(* Logix 5000 project; controller MyControlLogix 1756-L63 rev 15.1; software revision 15.02; part 3 of 4 *)
(* tags used below, declared in another part *)
   AFC56 : AFC;
(* MainProgram, continued *)

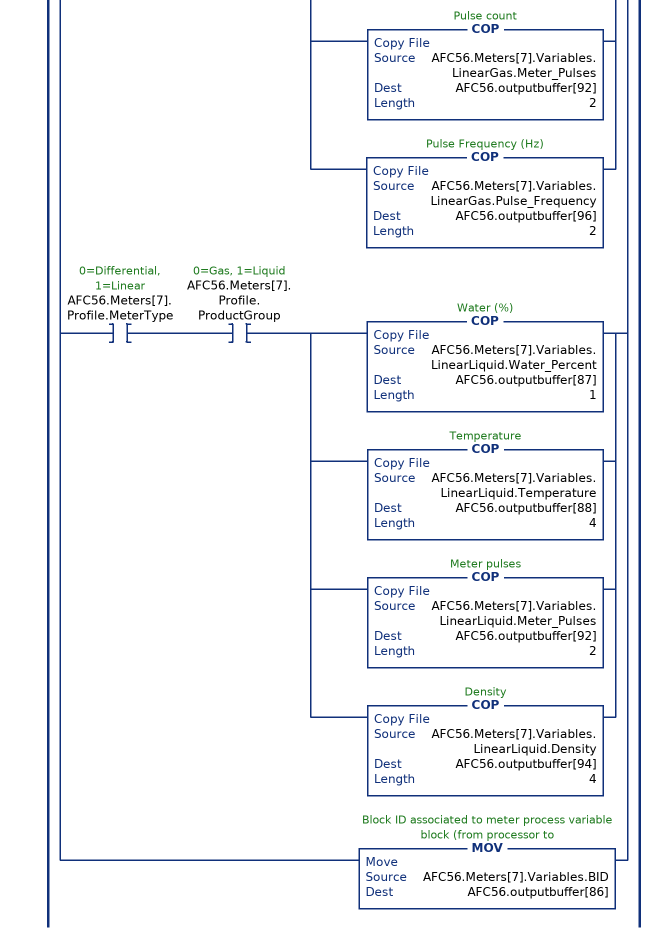
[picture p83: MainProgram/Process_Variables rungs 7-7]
   7: [ADD(8,8192,AFC56.Meters[7].Variables.BID) ,XIO(AFC56.EnableStatus.Meter8) [OTE(AFC56.Meters[7].Variables.BID.8) ,OTU(AFC56.DisableMeter.Meter8) ] ,XIC(AFC56.EnableStatus.Meter8) OTU(AFC56.EnableMeter.Meter8) ,XIO(AFC56.Meters[7].Profile.MeterType) XIO(AFC56.Meters[7].Profile.ProductGroup) COP(AFC56.Meters[7].Variables.DifferentialGas.Temperature,AFC56.outputbuffer[88],6) ,XIO(AFC56.Meters[7].Profile.MeterType) XIC(AFC56.Meters[7].Profile.ProductGroup) [COP(AFC56.Meters[7].Variables.DifferentialLiquid.Water_Percent,AFC56.outputbuffer[87],1) ,COP(AFC56.Meters[7].Variables.DifferentialLiquid.Temperature,AFC56.outputbuffer[88],8) ] ,XIC(AFC56.Meters[7].Profile.MeterType) XIO(AFC56.Meters[7].Profile.ProductGroup) [COP(AFC56.Meters[7].Variables.LinearGas.Temperature,AFC56.outputbuffer[88],4) ,COP(AFC56.Meters[7].Variables.LinearGas.Meter_Pulses,AFC56.outputbuffer[92],2) ,COP(AFC56.Meters[7].Variables.LinearGas.Pulse_Frequency,AFC56.outputbuffer[96],2) ] ,XIC(AFC56.Meters[7].Profile.MeterType) XIC(AFC56.Meters[7].Profile.ProductGroup) [COP(AFC56.Meters[7].Variables.LinearLiquid.Water_Percent,AFC56.outputbuffer[87],1) ,COP(AFC56.Meters[7].Variables.LinearLiquid.Temperature,AFC56.outputbuffer[88],4) ,COP(AFC56.Meters[7].Variables.LinearLiquid.Meter_Pulses,AFC56.outputbuffer[92],2) ,COP(AFC56.Meters[7].Variables.LinearLiquid.Density,AFC56.outputbuffer[94],4) ] ,MOV(AFC56.Meters[7].Variables.BID,AFC56.outputbuffer[86]) ];
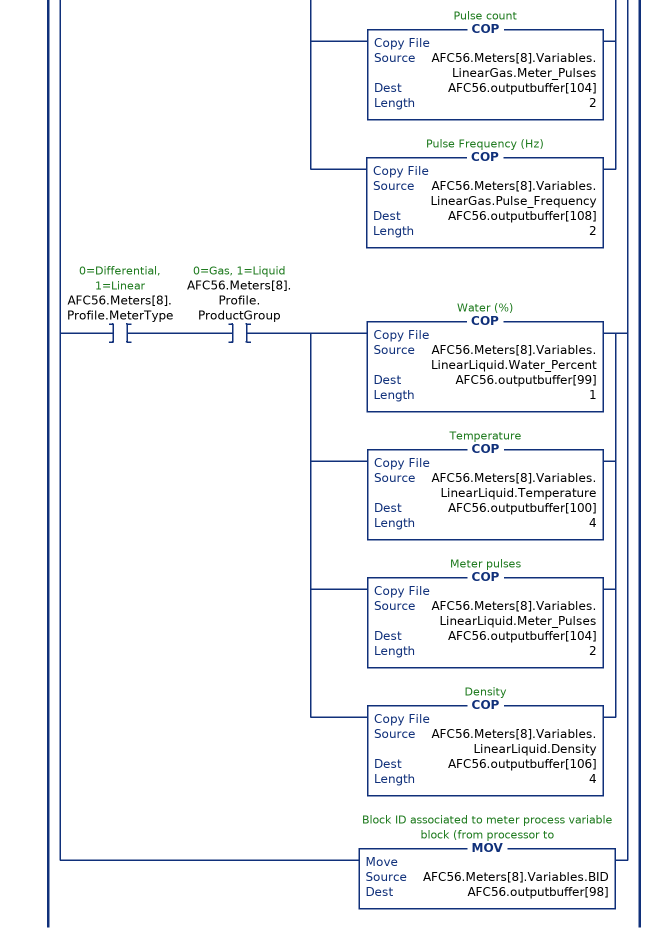
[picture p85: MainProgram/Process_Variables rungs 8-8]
   8: [ADD(9,8192,AFC56.Meters[8].Variables.BID) ,XIO(AFC56.EnableStatus.Meter9) [OTE(AFC56.Meters[8].Variables.BID.8) ,OTU(AFC56.DisableMeter.Meter9) ] ,XIC(AFC56.EnableStatus.Meter9) OTU(AFC56.EnableMeter.Meter9) ,XIO(AFC56.Meters[8].Profile.MeterType) XIO(AFC56.Meters[8].Profile.ProductGroup) COP(AFC56.Meters[8].Variables.DifferentialGas.Temperature,AFC56.outputbuffer[100],6) ,XIO(AFC56.Meters[8].Profile.MeterType) XIC(AFC56.Meters[8].Profile.ProductGroup) [COP(AFC56.Meters[8].Variables.DifferentialLiquid.Water_Percent,AFC56.outputbuffer[99],1) ,COP(AFC56.Meters[8].Variables.DifferentialLiquid.Temperature,AFC56.outputbuffer[100],8) ] ,XIC(AFC56.Meters[8].Profile.MeterType) XIO(AFC56.Meters[8].Profile.ProductGroup) [COP(AFC56.Meters[8].Variables.LinearGas.Temperature,AFC56.outputbuffer[100],4) ,COP(AFC56.Meters[8].Variables.LinearGas.Meter_Pulses,AFC56.outputbuffer[104],2) ,COP(AFC56.Meters[8].Variables.LinearGas.Pulse_Frequency,AFC56.outputbuffer[108],2) ] ,XIC(AFC56.Meters[8].Profile.MeterType) XIC(AFC56.Meters[8].Profile.ProductGroup) [COP(AFC56.Meters[8].Variables.LinearLiquid.Water_Percent,AFC56.outputbuffer[99],1) ,COP(AFC56.Meters[8].Variables.LinearLiquid.Temperature,AFC56.outputbuffer[100],4) ,COP(AFC56.Meters[8].Variables.LinearLiquid.Meter_Pulses,AFC56.outputbuffer[104],2) ,COP(AFC56.Meters[8].Variables.LinearLiquid.Density,AFC56.outputbuffer[106],4) ] ,MOV(AFC56.Meters[8].Variables.BID,AFC56.outputbuffer[98]) ];
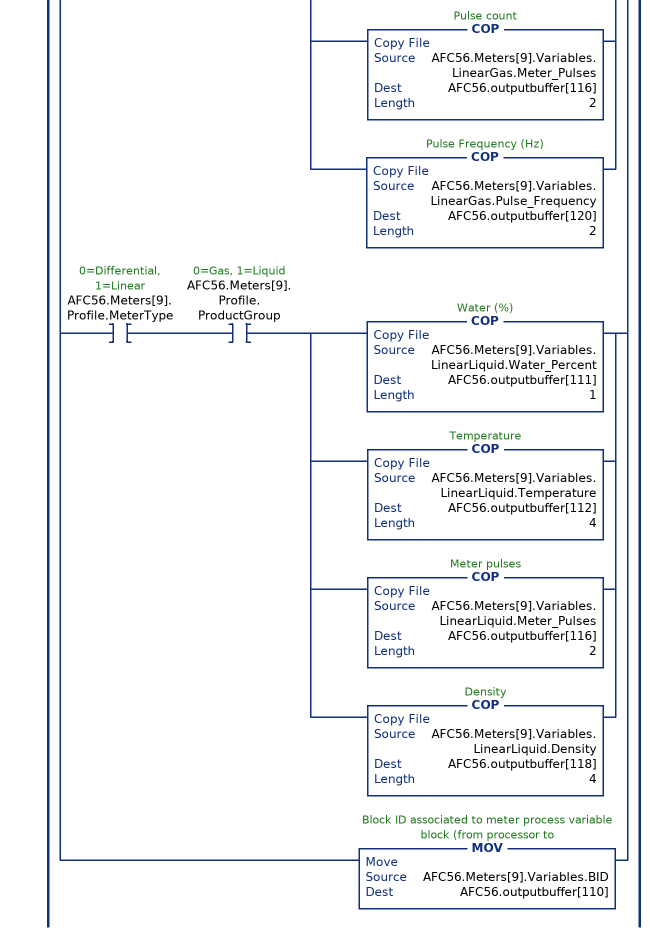
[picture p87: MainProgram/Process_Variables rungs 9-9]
   9: [ADD(10,8192,AFC56.Meters[9].Variables.BID) ,XIO(AFC56.EnableStatus.Meter10) [OTE(AFC56.Meters[9].Variables.BID.8) ,OTU(AFC56.DisableMeter.Meter10) ] ,XIC(AFC56.EnableStatus.Meter10) OTU(AFC56.EnableMeter.Meter10) ,XIO(AFC56.Meters[9].Profile.MeterType) XIO(AFC56.Meters[9].Profile.ProductGroup) COP(AFC56.Meters[9].Variables.DifferentialGas.Temperature,AFC56.outputbuffer[112],6) ,XIO(AFC56.Meters[9].Profile.MeterType) XIC(AFC56.Meters[9].Profile.ProductGroup) [COP(AFC56.Meters[9].Variables.DifferentialLiquid.Water_Percent,AFC56.outputbuffer[111],1) ,COP(AFC56.Meters[9].Variables.DifferentialLiquid.Temperature,AFC56.outputbuffer[112],8) ] ,XIC(AFC56.Meters[9].Profile.MeterType) XIO(AFC56.Meters[9].Profile.ProductGroup) [COP(AFC56.Meters[9].Variables.LinearGas.Temperature,AFC56.outputbuffer[112],4) ,COP(AFC56.Meters[9].Variables.LinearGas.Meter_Pulses,AFC56.outputbuffer[116],2) ,COP(AFC56.Meters[9].Variables.LinearGas.Pulse_Frequency,AFC56.outputbuffer[120],2) ] ,XIC(AFC56.Meters[9].Profile.MeterType) XIC(AFC56.Meters[9].Profile.ProductGroup) [COP(AFC56.Meters[9].Variables.LinearLiquid.Water_Percent,AFC56.outputbuffer[111],1) ,COP(AFC56.Meters[9].Variables.LinearLiquid.Temperature,AFC56.outputbuffer[112],4) ,COP(AFC56.Meters[9].Variables.LinearLiquid.Meter_Pulses,AFC56.outputbuffer[116],2) ,COP(AFC56.Meters[9].Variables.LinearLiquid.Density,AFC56.outputbuffer[118],4) ] ,MOV(AFC56.Meters[9].Variables.BID,AFC56.outputbuffer[110]) ];
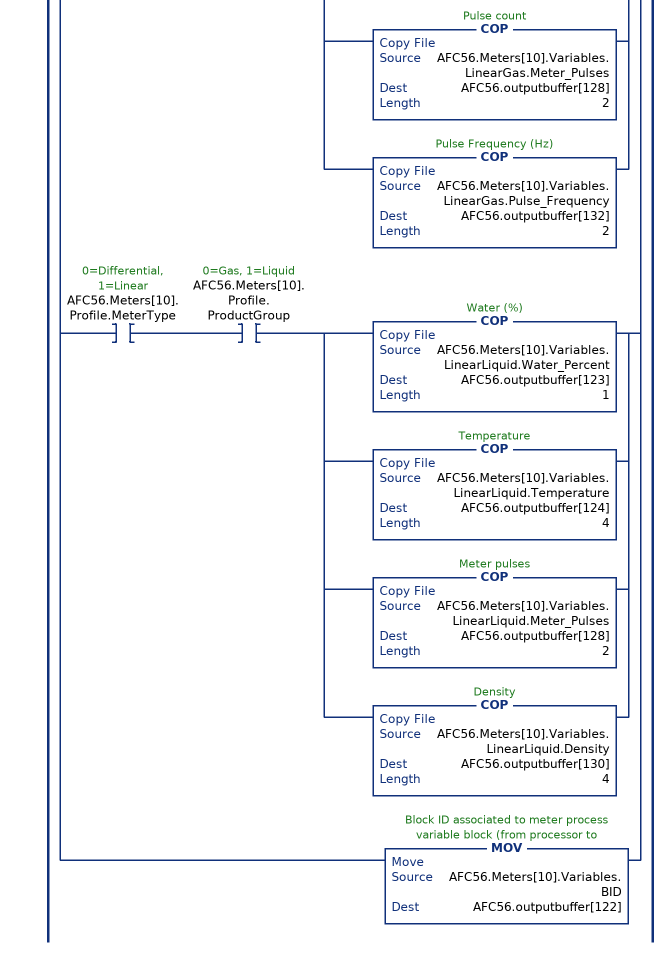
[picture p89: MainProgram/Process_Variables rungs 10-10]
   10: [ADD(11,8192,AFC56.Meters[10].Variables.BID) ,XIO(AFC56.EnableStatus.Meter11) [OTE(AFC56.Meters[10].Variables.BID.8) ,OTU(AFC56.DisableMeter.Meter11) ] ,XIC(AFC56.EnableStatus.Meter11) OTU(AFC56.EnableMeter.Meter11) ,XIO(AFC56.Meters[10].Profile.MeterType) XIO(AFC56.Meters[10].Profile.ProductGroup) COP(AFC56.Meters[10].Variables.DifferentialGas.Temperature,AFC56.outputbuffer[124],6) ,XIO(AFC56.Meters[10].Profile.MeterType) XIC(AFC56.Meters[10].Profile.ProductGroup) [COP(AFC56.Meters[10].Variables.DifferentialLiquid.Water_Percent,AFC56.outputbuffer[123],1) ,COP(AFC56.Meters[10].Variables.DifferentialLiquid.Temperature,AFC56.outputbuffer[124],8) ] ,XIC(AFC56.Meters[10].Profile.MeterType) XIO(AFC56.Meters[10].Profile.ProductGroup) [COP(AFC56.Meters[10].Variables.LinearGas.Temperature,AFC56.outputbuffer[124],4) ,COP(AFC56.Meters[10].Variables.LinearGas.Meter_Pulses,AFC56.outputbuffer[128],2) ,COP(AFC56.Meters[10].Variables.LinearGas.Pulse_Frequency,AFC56.outputbuffer[132],2) ] ,XIC(AFC56.Meters[10].Profile.MeterType) XIC(AFC56.Meters[10].Profile.ProductGroup) [COP(AFC56.Meters[10].Variables.LinearLiquid.Water_Percent,AFC56.outputbuffer[123],1) ,COP(AFC56.Meters[10].Variables.LinearLiquid.Temperature,AFC56.outputbuffer[124],4) ,COP(AFC56.Meters[10].Variables.LinearLiquid.Meter_Pulses,AFC56.outputbuffer[128],2) ,COP(AFC56.Meters[10].Variables.LinearLiquid.Density,AFC56.outputbuffer[130],4) ] ,MOV(AFC56.Meters[10].Variables.BID,AFC56.outputbuffer[122]) ];
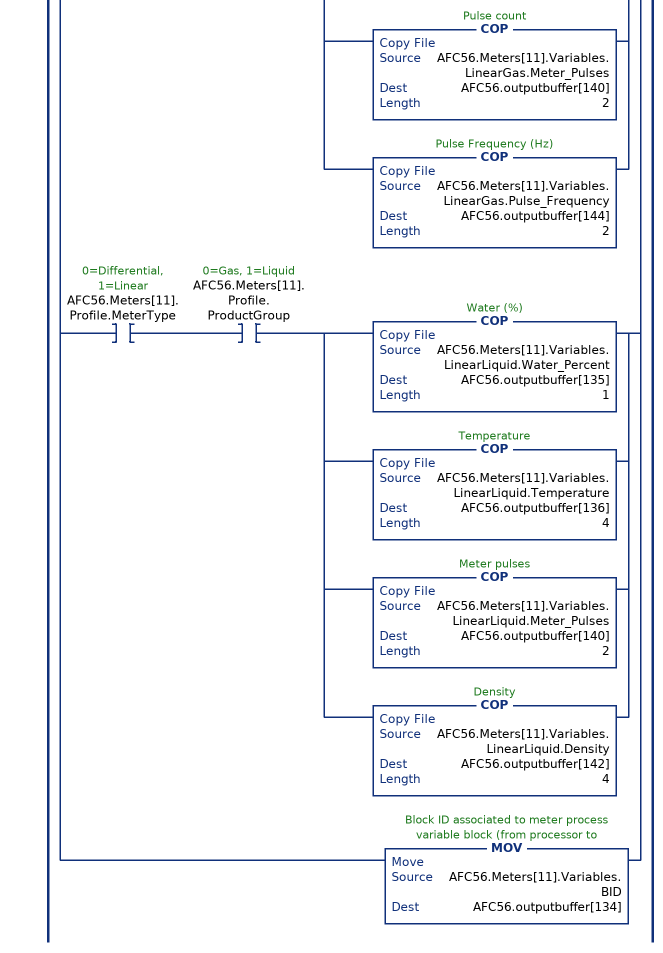
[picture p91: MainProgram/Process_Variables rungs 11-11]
   11: [ADD(12,8192,AFC56.Meters[11].Variables.BID) ,XIO(AFC56.EnableStatus.Meter12) [OTE(AFC56.Meters[11].Variables.BID.8) ,OTU(AFC56.DisableMeter.Meter12) ] ,XIC(AFC56.EnableStatus.Meter12) OTU(AFC56.EnableMeter.Meter12) ,XIO(AFC56.Meters[11].Profile.MeterType) XIO(AFC56.Meters[11].Profile.ProductGroup) COP(AFC56.Meters[11].Variables.DifferentialGas.Temperature,AFC56.outputbuffer[136],6) ,XIO(AFC56.Meters[11].Profile.MeterType) XIC(AFC56.Meters[11].Profile.ProductGroup) [COP(AFC56.Meters[11].Variables.DifferentialLiquid.Water_Percent,AFC56.outputbuffer[135],1) ,COP(AFC56.Meters[11].Variables.DifferentialLiquid.Temperature,AFC56.outputbuffer[136],8) ] ,XIC(AFC56.Meters[11].Profile.MeterType) XIO(AFC56.Meters[11].Profile.ProductGroup) [COP(AFC56.Meters[11].Variables.LinearGas.Temperature,AFC56.outputbuffer[136],4) ,COP(AFC56.Meters[11].Variables.LinearGas.Meter_Pulses,AFC56.outputbuffer[140],2) ,COP(AFC56.Meters[11].Variables.LinearGas.Pulse_Frequency,AFC56.outputbuffer[144],2) ] ,XIC(AFC56.Meters[11].Profile.MeterType) XIC(AFC56.Meters[11].Profile.ProductGroup) [COP(AFC56.Meters[11].Variables.LinearLiquid.Water_Percent,AFC56.outputbuffer[135],1) ,COP(AFC56.Meters[11].Variables.LinearLiquid.Temperature,AFC56.outputbuffer[136],4) ,COP(AFC56.Meters[11].Variables.LinearLiquid.Meter_Pulses,AFC56.outputbuffer[140],2) ,COP(AFC56.Meters[11].Variables.LinearLiquid.Density,AFC56.outputbuffer[142],4) ] ,MOV(AFC56.Meters[11].Variables.BID,AFC56.outputbuffer[134]) ];
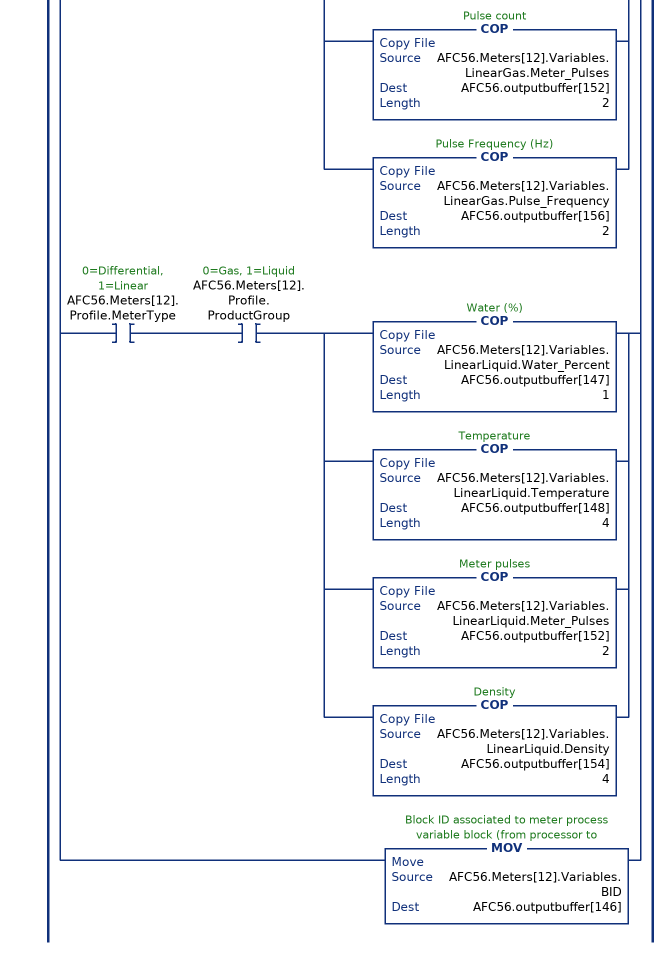
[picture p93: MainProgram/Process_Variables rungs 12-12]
   12: [ADD(13,8192,AFC56.Meters[12].Variables.BID) ,XIO(AFC56.EnableStatus.Meter13) [OTE(AFC56.Meters[12].Variables.BID.8) ,OTU(AFC56.DisableMeter.Meter13) ] ,XIC(AFC56.EnableStatus.Meter13) OTU(AFC56.EnableMeter.Meter13) ,XIO(AFC56.Meters[12].Profile.MeterType) XIO(AFC56.Meters[12].Profile.ProductGroup) COP(AFC56.Meters[12].Variables.DifferentialGas.Temperature,AFC56.outputbuffer[148],6) ,XIO(AFC56.Meters[12].Profile.MeterType) XIC(AFC56.Meters[12].Profile.ProductGroup) [COP(AFC56.Meters[12].Variables.DifferentialLiquid.Water_Percent,AFC56.outputbuffer[147],1) ,COP(AFC56.Meters[12].Variables.DifferentialLiquid.Temperature,AFC56.outputbuffer[148],8) ] ,XIC(AFC56.Meters[12].Profile.MeterType) XIO(AFC56.Meters[12].Profile.ProductGroup) [COP(AFC56.Meters[12].Variables.LinearGas.Temperature,AFC56.outputbuffer[148],4) ,COP(AFC56.Meters[12].Variables.LinearGas.Meter_Pulses,AFC56.outputbuffer[152],2) ,COP(AFC56.Meters[12].Variables.LinearGas.Pulse_Frequency,AFC56.outputbuffer[156],2) ] ,XIC(AFC56.Meters[12].Profile.MeterType) XIC(AFC56.Meters[12].Profile.ProductGroup) [COP(AFC56.Meters[12].Variables.LinearLiquid.Water_Percent,AFC56.outputbuffer[147],1) ,COP(AFC56.Meters[12].Variables.LinearLiquid.Temperature,AFC56.outputbuffer[148],4) ,COP(AFC56.Meters[12].Variables.LinearLiquid.Meter_Pulses,AFC56.outputbuffer[152],2) ,COP(AFC56.Meters[12].Variables.LinearLiquid.Density,AFC56.outputbuffer[154],4) ] ,MOV(AFC56.Meters[12].Variables.BID,AFC56.outputbuffer[146]) ];
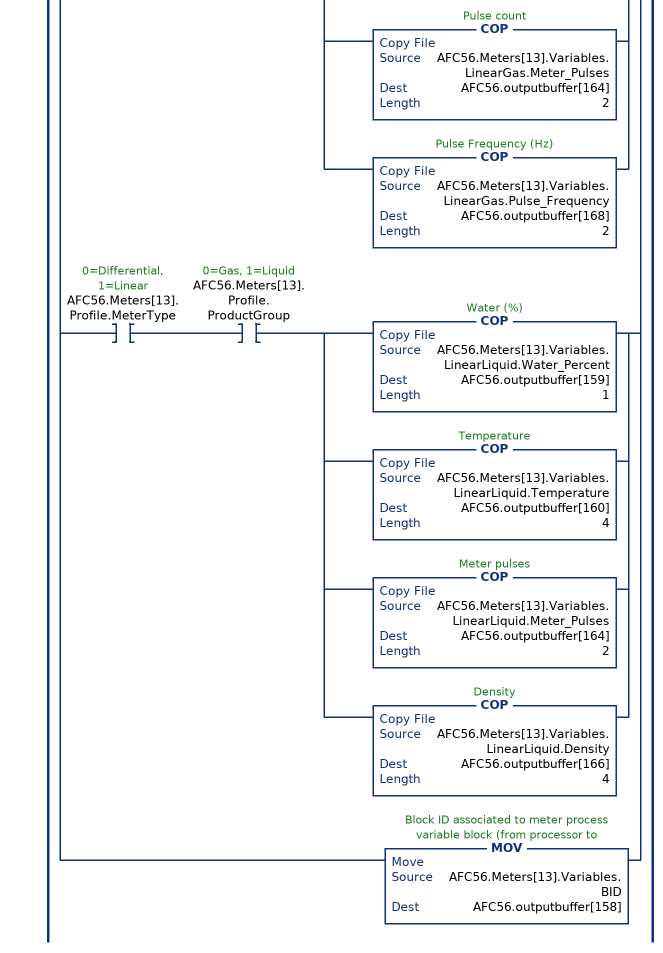
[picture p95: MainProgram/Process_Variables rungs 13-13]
   13: [ADD(14,8192,AFC56.Meters[13].Variables.BID) ,XIO(AFC56.EnableStatus.Meter14) [OTE(AFC56.Meters[13].Variables.BID.8) ,OTU(AFC56.DisableMeter.Meter14) ] ,XIC(AFC56.EnableStatus.Meter14) OTU(AFC56.EnableMeter.Meter14) ,XIO(AFC56.Meters[13].Profile.MeterType) XIO(AFC56.Meters[13].Profile.ProductGroup) COP(AFC56.Meters[13].Variables.DifferentialGas.Temperature,AFC56.outputbuffer[160],6) ,XIO(AFC56.Meters[13].Profile.MeterType) XIC(AFC56.Meters[13].Profile.ProductGroup) [COP(AFC56.Meters[13].Variables.DifferentialLiquid.Water_Percent,AFC56.outputbuffer[159],1) ,COP(AFC56.Meters[13].Variables.DifferentialLiquid.Temperature,AFC56.outputbuffer[160],8) ] ,XIC(AFC56.Meters[13].Profile.MeterType) XIO(AFC56.Meters[13].Profile.ProductGroup) [COP(AFC56.Meters[13].Variables.LinearGas.Temperature,AFC56.outputbuffer[160],4) ,COP(AFC56.Meters[13].Variables.LinearGas.Meter_Pulses,AFC56.outputbuffer[164],2) ,COP(AFC56.Meters[13].Variables.LinearGas.Pulse_Frequency,AFC56.outputbuffer[168],2) ] ,XIC(AFC56.Meters[13].Profile.MeterType) XIC(AFC56.Meters[13].Profile.ProductGroup) [COP(AFC56.Meters[13].Variables.LinearLiquid.Water_Percent,AFC56.outputbuffer[159],1) ,COP(AFC56.Meters[13].Variables.LinearLiquid.Temperature,AFC56.outputbuffer[160],4) ,COP(AFC56.Meters[13].Variables.LinearLiquid.Meter_Pulses,AFC56.outputbuffer[164],2) ,COP(AFC56.Meters[13].Variables.LinearLiquid.Density,AFC56.outputbuffer[166],4) ] ,MOV(AFC56.Meters[13].Variables.BID,AFC56.outputbuffer[158]) ];
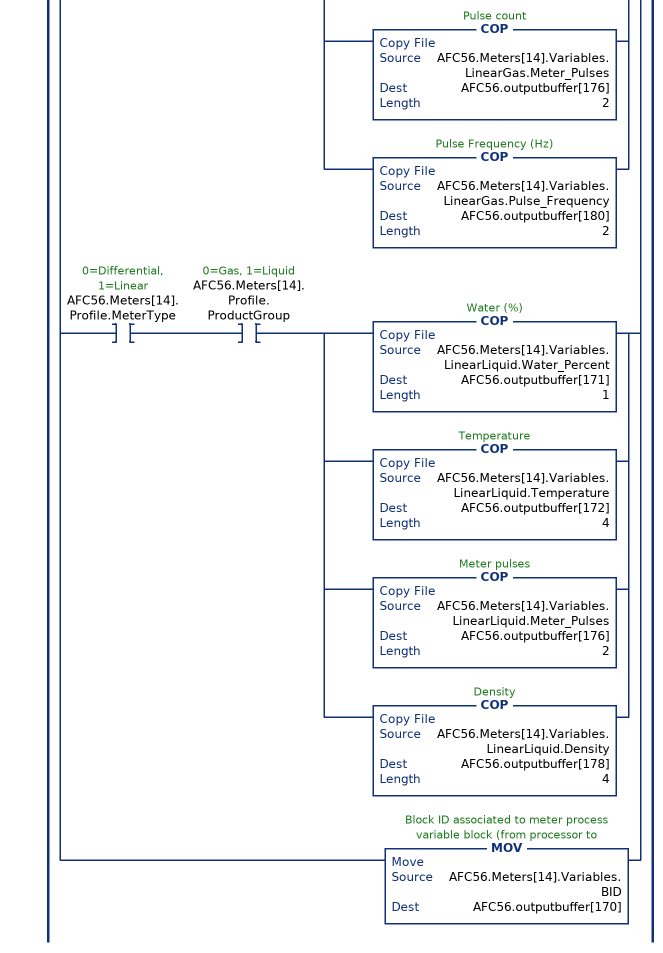
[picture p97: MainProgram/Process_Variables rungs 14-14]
   14: [ADD(15,8192,AFC56.Meters[14].Variables.BID) ,XIO(AFC56.EnableStatus.Meter15) [OTE(AFC56.Meters[14].Variables.BID.8) ,OTU(AFC56.DisableMeter.Meter15) ] ,XIC(AFC56.EnableStatus.Meter15) OTU(AFC56.EnableMeter.Meter15) ,XIO(AFC56.Meters[14].Profile.MeterType) XIO(AFC56.Meters[14].Profile.ProductGroup) COP(AFC56.Meters[14].Variables.DifferentialGas.Temperature,AFC56.outputbuffer[172],6) ,XIO(AFC56.Meters[14].Profile.MeterType) XIC(AFC56.Meters[14].Profile.ProductGroup) [COP(AFC56.Meters[14].Variables.DifferentialLiquid.Water_Percent,AFC56.outputbuffer[171],1) ,COP(AFC56.Meters[14].Variables.DifferentialLiquid.Temperature,AFC56.outputbuffer[172],8) ] ,XIC(AFC56.Meters[14].Profile.MeterType) XIO(AFC56.Meters[14].Profile.ProductGroup) [COP(AFC56.Meters[14].Variables.LinearGas.Temperature,AFC56.outputbuffer[172],4) ,COP(AFC56.Meters[14].Variables.LinearGas.Meter_Pulses,AFC56.outputbuffer[176],2) ,COP(AFC56.Meters[14].Variables.LinearGas.Pulse_Frequency,AFC56.outputbuffer[180],2) ] ,XIC(AFC56.Meters[14].Profile.MeterType) XIC(AFC56.Meters[14].Profile.ProductGroup) [COP(AFC56.Meters[14].Variables.LinearLiquid.Water_Percent,AFC56.outputbuffer[171],1) ,COP(AFC56.Meters[14].Variables.LinearLiquid.Temperature,AFC56.outputbuffer[172],4) ,COP(AFC56.Meters[14].Variables.LinearLiquid.Meter_Pulses,AFC56.outputbuffer[176],2) ,COP(AFC56.Meters[14].Variables.LinearLiquid.Density,AFC56.outputbuffer[178],4) ] ,MOV(AFC56.Meters[14].Variables.BID,AFC56.outputbuffer[170]) ];
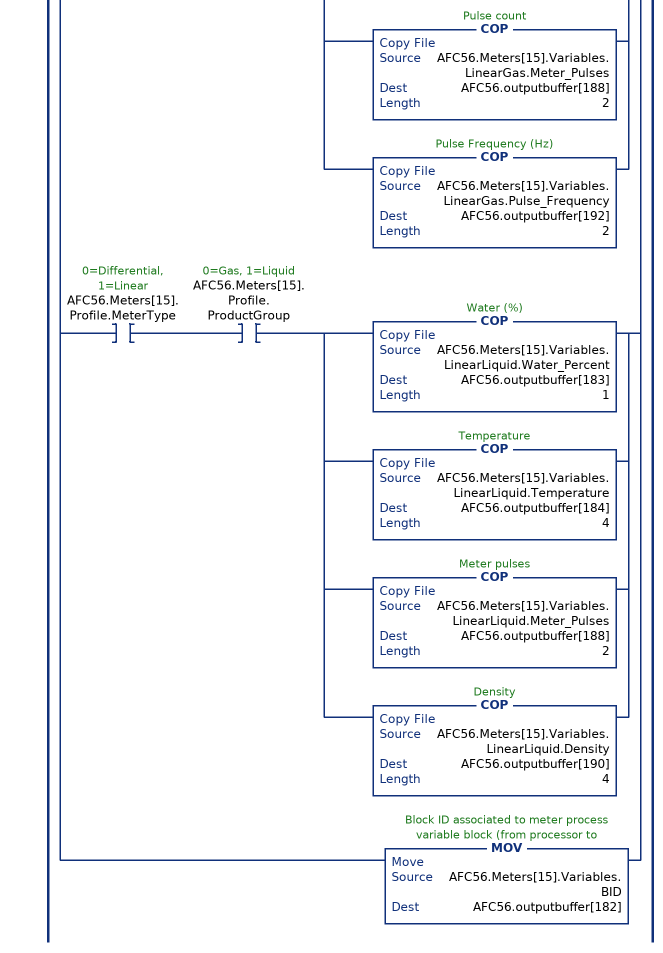
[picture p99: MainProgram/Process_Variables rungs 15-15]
   15: [ADD(16,8192,AFC56.Meters[15].Variables.BID) ,XIO(AFC56.EnableStatus.Meter16) [OTE(AFC56.Meters[15].Variables.BID.8) ,OTU(AFC56.DisableMeter.Meter16) ] ,XIC(AFC56.EnableStatus.Meter16) OTU(AFC56.EnableMeter.Meter16) ,XIO(AFC56.Meters[15].Profile.MeterType) XIO(AFC56.Meters[15].Profile.ProductGroup) COP(AFC56.Meters[15].Variables.DifferentialGas.Temperature,AFC56.outputbuffer[184],6) ,XIO(AFC56.Meters[15].Profile.MeterType) XIC(AFC56.Meters[15].Profile.ProductGroup) [COP(AFC56.Meters[15].Variables.DifferentialLiquid.Water_Percent,AFC56.outputbuffer[183],1) ,COP(AFC56.Meters[15].Variables.DifferentialLiquid.Temperature,AFC56.outputbuffer[184],8) ] ,XIC(AFC56.Meters[15].Profile.MeterType) XIO(AFC56.Meters[15].Profile.ProductGroup) [COP(AFC56.Meters[15].Variables.LinearGas.Temperature,AFC56.outputbuffer[184],4) ,COP(AFC56.Meters[15].Variables.LinearGas.Meter_Pulses,AFC56.outputbuffer[188],2) ,COP(AFC56.Meters[15].Variables.LinearGas.Pulse_Frequency,AFC56.outputbuffer[192],2) ] ,XIC(AFC56.Meters[15].Profile.MeterType) XIC(AFC56.Meters[15].Profile.ProductGroup) [COP(AFC56.Meters[15].Variables.LinearLiquid.Water_Percent,AFC56.outputbuffer[183],1) ,COP(AFC56.Meters[15].Variables.LinearLiquid.Temperature,AFC56.outputbuffer[184],4) ,COP(AFC56.Meters[15].Variables.LinearLiquid.Meter_Pulses,AFC56.outputbuffer[188],2) ,COP(AFC56.Meters[15].Variables.LinearLiquid.Density,AFC56.outputbuffer[190],4) ] ,MOV(AFC56.Meters[15].Variables.BID,AFC56.outputbuffer[182]) ];
END_ROUTINE

ROUTINE Prove_In   (* ladder *)
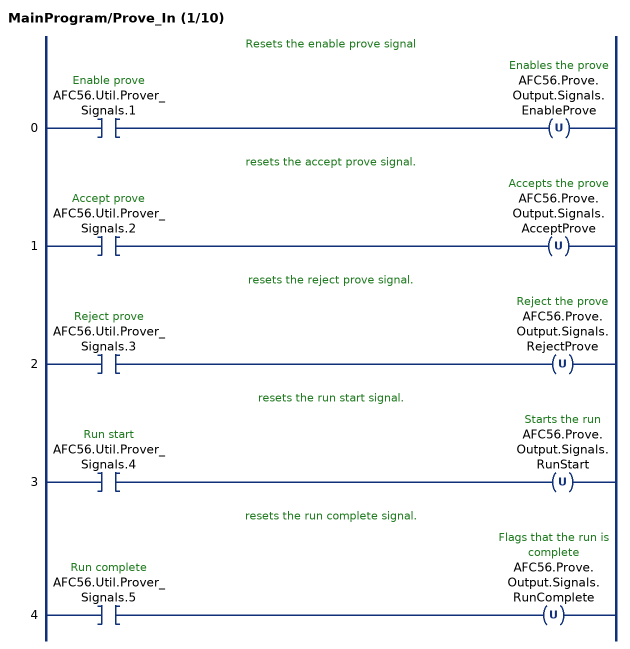
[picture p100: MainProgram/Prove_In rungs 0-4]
   // Resets the enable prove signal
   0: XIC(AFC56.Util.Prover_Signals.1)OTU(AFC56.Prove.Output.Signals.EnableProve);
   // resets the accept prove signal.
   1: XIC(AFC56.Util.Prover_Signals.2)OTU(AFC56.Prove.Output.Signals.AcceptProve);
   // resets the reject prove signal.
   2: XIC(AFC56.Util.Prover_Signals.3)OTU(AFC56.Prove.Output.Signals.RejectProve);
   // resets the run start signal.
   3: XIC(AFC56.Util.Prover_Signals.4)OTU(AFC56.Prove.Output.Signals.RunStart);
   // resets the run complete signal.
   4: XIC(AFC56.Util.Prover_Signals.5)OTU(AFC56.Prove.Output.Signals.RunComplete);
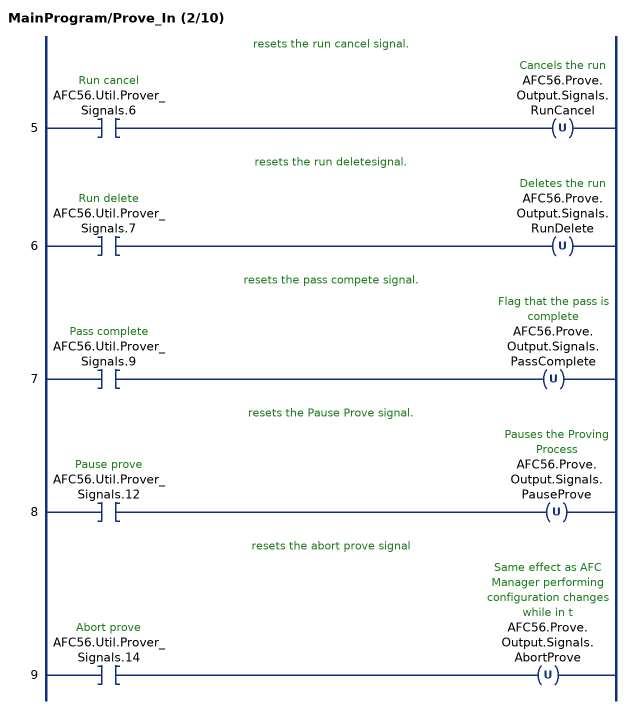
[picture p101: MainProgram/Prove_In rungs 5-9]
   // resets the run cancel signal.
   5: XIC(AFC56.Util.Prover_Signals.6)OTU(AFC56.Prove.Output.Signals.RunCancel);
   // resets the run deletesignal.
   6: XIC(AFC56.Util.Prover_Signals.7)OTU(AFC56.Prove.Output.Signals.RunDelete);
   // resets the pass compete signal.
   7: XIC(AFC56.Util.Prover_Signals.9)OTU(AFC56.Prove.Output.Signals.PassComplete);
   // resets the Pause Prove signal.
   8: XIC(AFC56.Util.Prover_Signals.12)OTU(AFC56.Prove.Output.Signals.PauseProve);
   // resets the abort prove signal
   9: XIC(AFC56.Util.Prover_Signals.14)OTU(AFC56.Prove.Output.Signals.AbortProve);
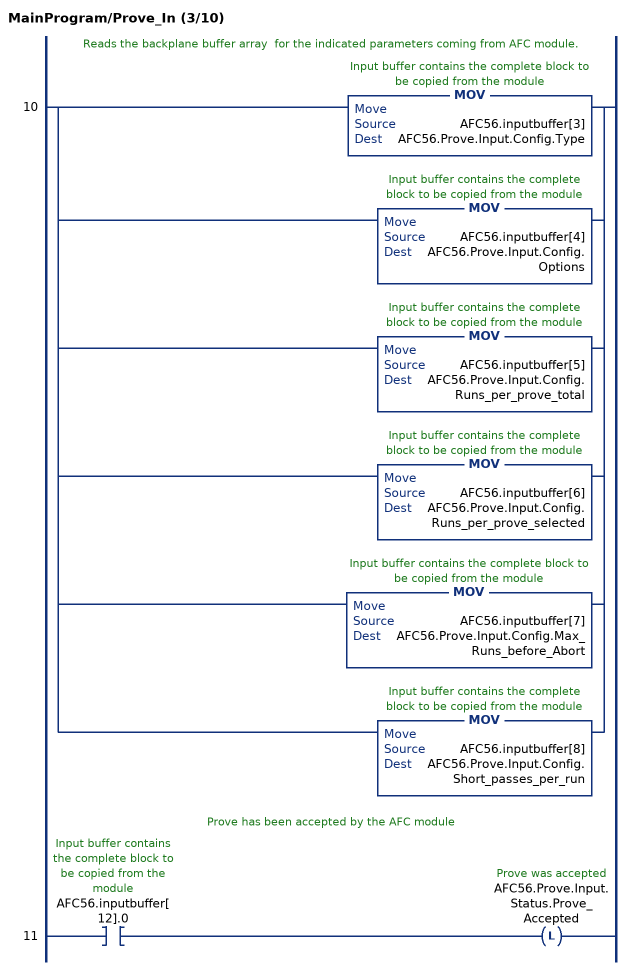
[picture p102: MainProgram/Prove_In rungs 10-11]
   // Reads the backplane buffer array  for the indicated parameters coming from AFC module.
   10: [MOV(AFC56.inputbuffer[3],AFC56.Prove.Input.Config.Type) ,MOV(AFC56.inputbuffer[4],AFC56.Prove.Input.Config.Options) ,MOV(AFC56.inputbuffer[5],AFC56.Prove.Input.Config.Runs_per_prove_total) ,MOV(AFC56.inputbuffer[6],AFC56.Prove.Input.Config.Runs_per_prove_selected) ,MOV(AFC56.inputbuffer[7],AFC56.Prove.Input.Config.Max_Runs_before_Abort) ,MOV(AFC56.inputbuffer[8],AFC56.Prove.Input.Config.Short_passes_per_run) ];
   // Prove has been accepted by the AFC module
   11: XIC(AFC56.inputbuffer[12].0)OTL(AFC56.Prove.Input.Status.Prove_Accepted);
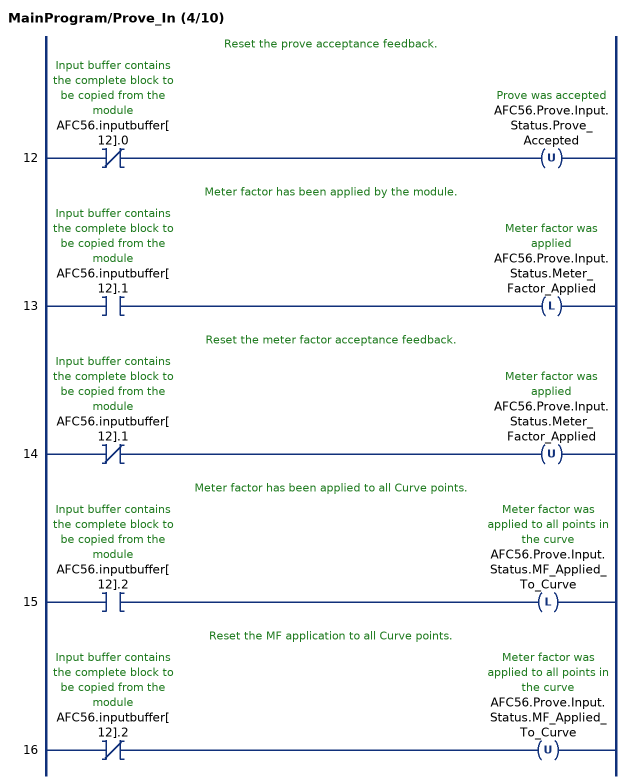
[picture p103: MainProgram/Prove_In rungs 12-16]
   // Reset the prove acceptance feedback.
   12: XIO(AFC56.inputbuffer[12].0)OTU(AFC56.Prove.Input.Status.Prove_Accepted);
   // Meter factor has been applied by the module.
   13: XIC(AFC56.inputbuffer[12].1)OTL(AFC56.Prove.Input.Status.Meter_Factor_Applied);
   // Reset the meter factor acceptance feedback.
   14: XIO(AFC56.inputbuffer[12].1)OTU(AFC56.Prove.Input.Status.Meter_Factor_Applied);
   // Meter factor has been applied to all Curve points.
   15: XIC(AFC56.inputbuffer[12].2)OTL(AFC56.Prove.Input.Status.MF_Applied_To_Curve);
   // Reset the MF application to all Curve points.
   16: XIO(AFC56.inputbuffer[12].2)OTU(AFC56.Prove.Input.Status.MF_Applied_To_Curve);
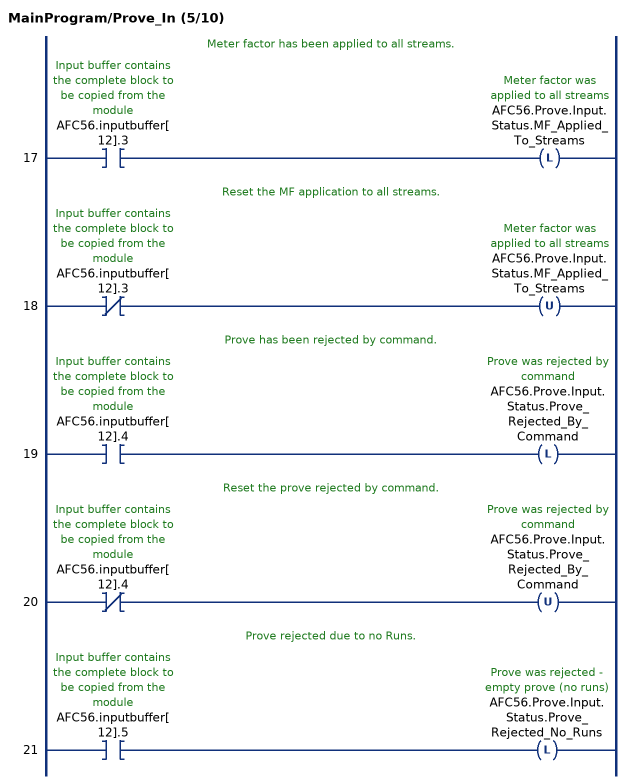
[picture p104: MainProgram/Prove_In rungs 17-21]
   // Meter factor has been applied to all streams.
   17: XIC(AFC56.inputbuffer[12].3)OTL(AFC56.Prove.Input.Status.MF_Applied_To_Streams);
   // Reset the MF application to all streams.
   18: XIO(AFC56.inputbuffer[12].3)OTU(AFC56.Prove.Input.Status.MF_Applied_To_Streams);
   // Prove has been rejected by command.
   19: XIC(AFC56.inputbuffer[12].4)OTL(AFC56.Prove.Input.Status.Prove_Rejected_By_Command);
   // Reset the prove rejected by command.
   20: XIO(AFC56.inputbuffer[12].4)OTU(AFC56.Prove.Input.Status.Prove_Rejected_By_Command);
   // Prove rejected due to no Runs.
   21: XIC(AFC56.inputbuffer[12].5)OTL(AFC56.Prove.Input.Status.Prove_Rejected_No_Runs);
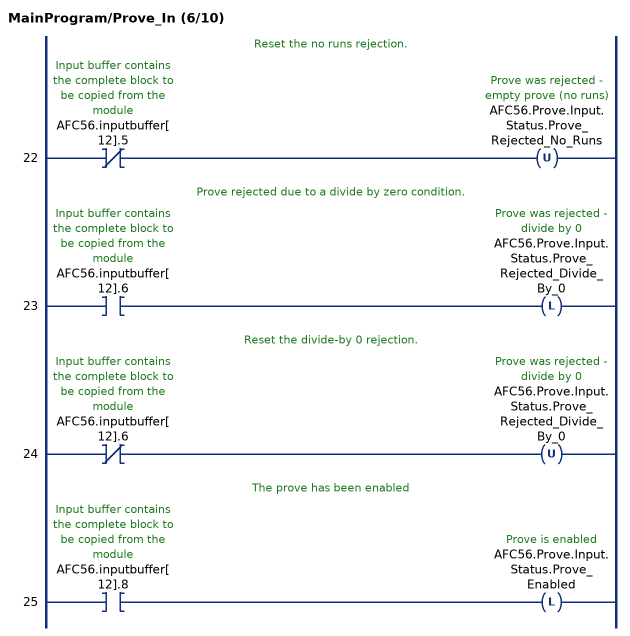
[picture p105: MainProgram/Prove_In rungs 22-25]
   // Reset the no runs rejection.
   22: XIO(AFC56.inputbuffer[12].5)OTU(AFC56.Prove.Input.Status.Prove_Rejected_No_Runs);
   // Prove rejected due to a divide by zero condition.
   23: XIC(AFC56.inputbuffer[12].6)OTL(AFC56.Prove.Input.Status.Prove_Rejected_Divide_By_0);
   // Reset the divide-by 0 rejection.
   24: XIO(AFC56.inputbuffer[12].6)OTU(AFC56.Prove.Input.Status.Prove_Rejected_Divide_By_0);
   // The prove has been enabled
   25: XIC(AFC56.inputbuffer[12].8)OTL(AFC56.Prove.Input.Status.Prove_Enabled);
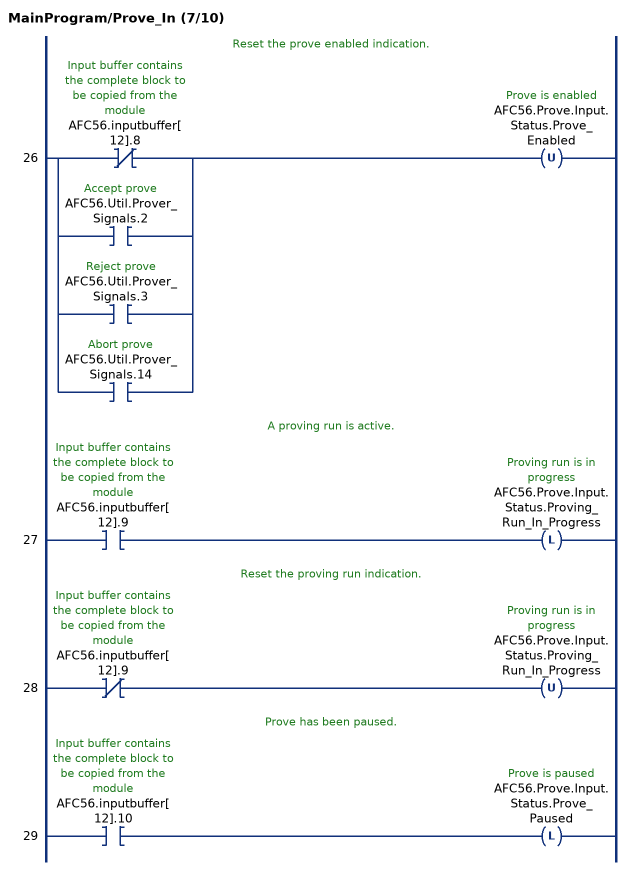
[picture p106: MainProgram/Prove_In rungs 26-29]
   // Reset the prove enabled indication.
   26: [XIO(AFC56.inputbuffer[12].8) ,XIC(AFC56.Util.Prover_Signals.2) ,XIC(AFC56.Util.Prover_Signals.3) ,XIC(AFC56.Util.Prover_Signals.14) ]OTU(AFC56.Prove.Input.Status.Prove_Enabled);
   // A proving run is active.
   27: XIC(AFC56.inputbuffer[12].9)OTL(AFC56.Prove.Input.Status.Proving_Run_In_Progress);
   // Reset the proving run indication.
   28: XIO(AFC56.inputbuffer[12].9)OTU(AFC56.Prove.Input.Status.Proving_Run_In_Progress);
   // Prove has been paused.
   29: XIC(AFC56.inputbuffer[12].10)OTL(AFC56.Prove.Input.Status.Prove_Paused);
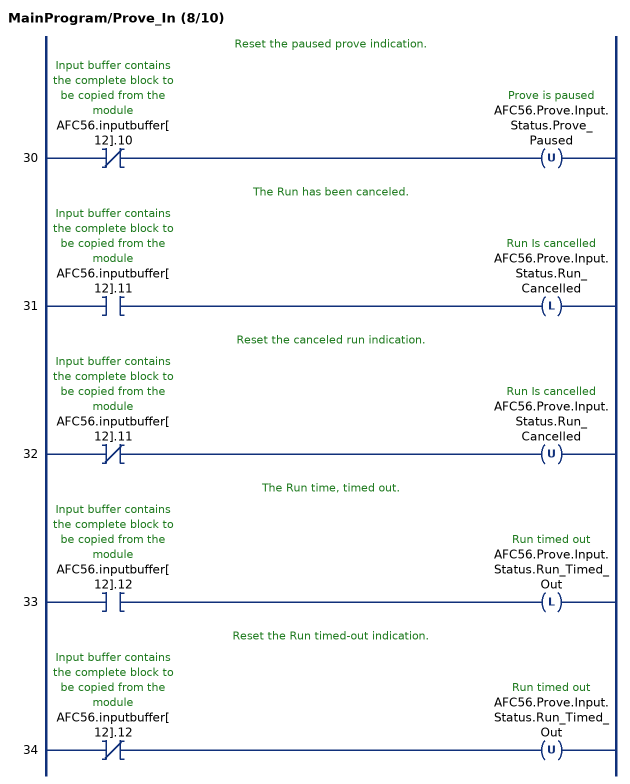
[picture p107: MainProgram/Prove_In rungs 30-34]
   // Reset the paused prove indication.
   30: XIO(AFC56.inputbuffer[12].10)OTU(AFC56.Prove.Input.Status.Prove_Paused);
   // The Run has been canceled.
   31: XIC(AFC56.inputbuffer[12].11)OTL(AFC56.Prove.Input.Status.Run_Cancelled);
   // Reset the canceled run indication.
   32: XIO(AFC56.inputbuffer[12].11)OTU(AFC56.Prove.Input.Status.Run_Cancelled);
   // The Run time, timed out.
   33: XIC(AFC56.inputbuffer[12].12)OTL(AFC56.Prove.Input.Status.Run_Timed_Out);
   // Reset the Run timed-out indication.
   34: XIO(AFC56.inputbuffer[12].12)OTU(AFC56.Prove.Input.Status.Run_Timed_Out);
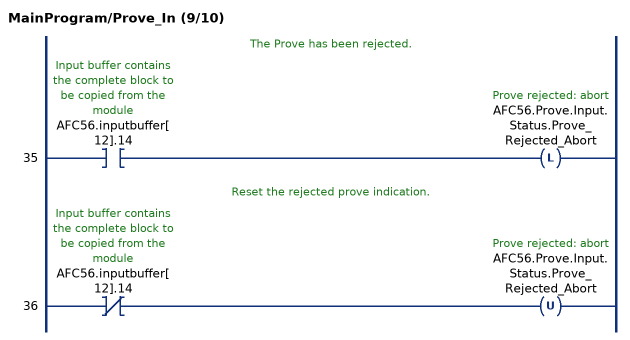
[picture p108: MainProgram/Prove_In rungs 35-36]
   // The Prove has been rejected.
   35: XIC(AFC56.inputbuffer[12].14)OTL(AFC56.Prove.Input.Status.Prove_Rejected_Abort);
   // Reset the rejected prove indication.
   36: XIO(AFC56.inputbuffer[12].14)OTU(AFC56.Prove.Input.Status.Prove_Rejected_Abort);
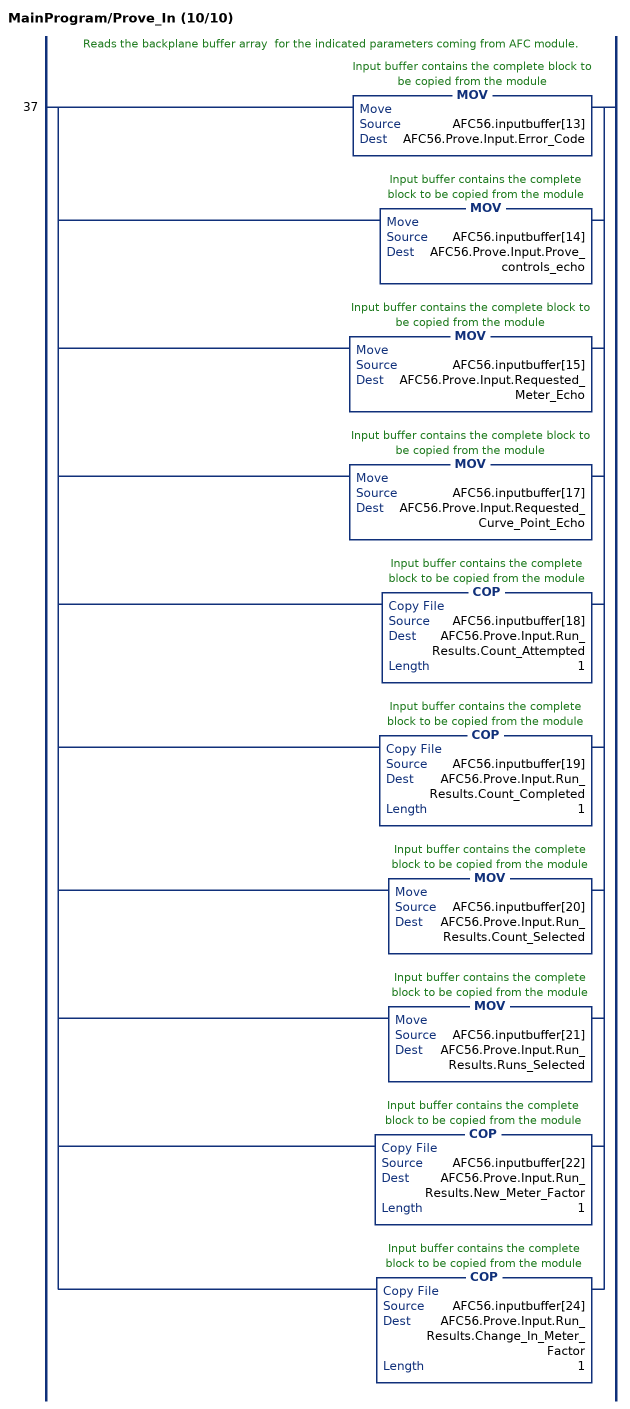
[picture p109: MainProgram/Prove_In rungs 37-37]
   // Reads the backplane buffer array  for the indicated parameters coming from AFC module.
   37: [MOV(AFC56.inputbuffer[13],AFC56.Prove.Input.Error_Code) ,MOV(AFC56.inputbuffer[14],AFC56.Prove.Input.Prove_controls_echo) ,MOV(AFC56.inputbuffer[15],AFC56.Prove.Input.Requested_Meter_Echo) ,MOV(AFC56.inputbuffer[17],AFC56.Prove.Input.Requested_Curve_Point_Echo) ,COP(AFC56.inputbuffer[18],AFC56.Prove.Input.Run_Results.Count_Attempted,1) ,COP(AFC56.inputbuffer[19],AFC56.Prove.Input.Run_Results.Count_Completed,1) ,MOV(AFC56.inputbuffer[20],AFC56.Prove.Input.Run_Results.Count_Selected) ,MOV(AFC56.inputbuffer[21],AFC56.Prove.Input.Run_Results.Runs_Selected) ,COP(AFC56.inputbuffer[22],AFC56.Prove.Input.Run_Results.New_Meter_Factor,1) ,COP(AFC56.inputbuffer[24],AFC56.Prove.Input.Run_Results.Change_In_Meter_Factor,1) ];
END_ROUTINE
